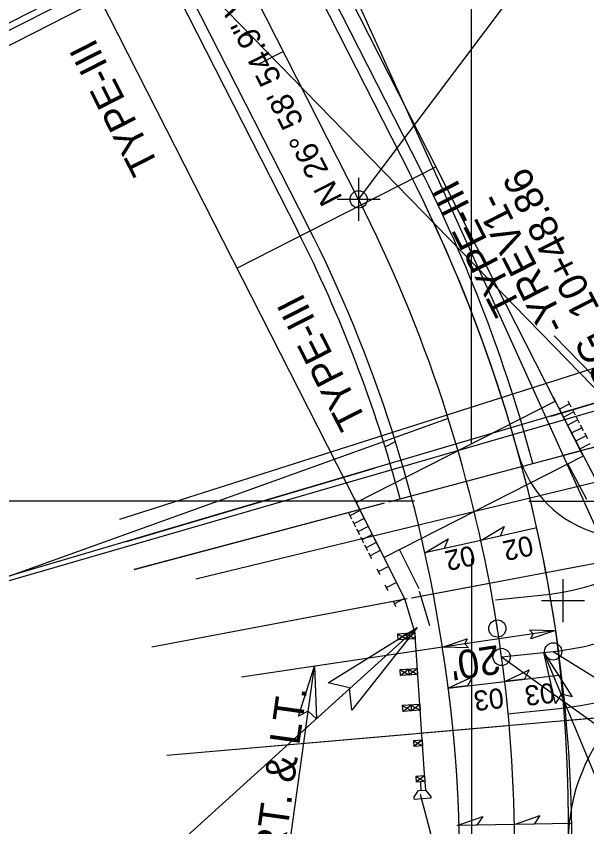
# Model space of a CAD drawing. Extents: x 557583 to 560285, y 513145 to 516544.
# Drawn here: x 559319.8 to 559419.4, y 515400.9 to 515542.3 of the extents above; entities that cross this region are included whole.
import ezdxf

# ---------------------------------------------------------------- set-up
doc = ezdxf.new("R2010")
doc.units = 0
for name, color, linetype in [('COGO Default Chain', 7, 'Continuous'), ('Default', 7, 'Continuous'), ('Exist Environmental Wetland Boundary', 7, 'Continuous'), ('Exist Environmental Wetland Boundary Cogo Point CELL', 7, 'Continuous'), ('Exist Hydro Jurisdictional Stream or Body of Water NEU Mitigable Cogo Comment', 7, 'Continuous'), ('Exist Hydro Jurisdictional Stream or Body of Water NEU Mitigable Cogo Elevation', 7, 'Continuous'), ('Exist Hydro Jurisdictional Stream or Body of Water NEU Mitigable Cogo Point CELL', 7, 'Continuous'), ('Exist Hydro Swamp or Marsh', 7, 'Continuous'), ('Prop Approach Slab', 7, 'Continuous'), ('Prop Dimension', 7, 'Continuous'), ('Prop DSN Text', 7, 'Continuous'), ('Prop EOT', 7, 'Continuous'), ('Prop Guardrail Anchor Unit CELL', 7, 'Continuous'), ('Prop Guardrail Shop Curved', 7, 'Continuous'), ('Prop Paved Shoulder', 7, 'Continuous'), ('Prop Roadway Bridge', 7, 'Continuous'), ('Prop SBG', 7, 'Continuous'), ('Prop Structure Anchor Unit CELL', 7, 'Continuous'), ('Prop Superelevation Label', 7, 'Continuous'), ('Prop Terminator CELL', 7, 'Continuous'), ('Scratch_Level_0', 7, 'Continuous'), ('Scratch_Level_1', 7, 'Continuous'), ('Scratch_Level_2', 7, 'Continuous'), ('Scratch_Level_3', 7, 'Continuous'), ('Scratch_Level_4', 7, 'Continuous'), ('Scratch_Level_6', 7, 'Continuous'), ('Scratch_Level_7', 7, 'Continuous'), ('Scratch_Level_8', 7, 'Continuous')]:
    doc.layers.add(name, color=color, linetype=linetype)

msp = doc.modelspace()

# ---------------------------------------------------------------- linework, layer by layer
at = {"layer": 'COGO Default Chain'}
for p, q in [((559379.56, 515514.07), (559379.56, 515506.57)), ((559383.31, 515510.32), (559375.81, 515510.32)), ((559415.21, 515444.06), (559415.21, 515436.56)), ((559418.96, 515440.31), (559411.46, 515440.31))]:
    msp.add_line(p, q, dxfattribs=at)
msp.add_arc((559156.78, 515396.89), 250, 352.0938, 26.9819, dxfattribs=at)
at = {"layer": 'Default'}
for p, q in [((559399.28, 515467.65), (559399.28, 515704.81)), ((559395.19, 515472.11), (559216.79, 515407.97)), ((559389.28, 515457.65), (558978.6, 515457.65)), ((559409.28, 515457.65), (559788.26, 515457.65)), ((559399.28, 515447.65), (559399.28, 515179.47))]:
    msp.add_line(p, q, dxfattribs=at)
at = {"layer": 'Exist Environmental Wetland Boundary'}
msp.add_line((559403.78, 515435.45), (559402.47, 515443.34), dxfattribs=at)
at = {"layer": 'Exist Environmental Wetland Boundary Cogo Point CELL'}
for p, q in [((559379.56, 515510.32), (559423.68, 515569.02)), ((559425.75, 515397.97), (559411.89, 515431.29)), ((559413.51, 515431.46), (559479.86, 515389.93)), ((559404.51, 515430.5), (559444.86, 515401.63))]:
    msp.add_line(p, q, dxfattribs=at)
for centre in [(559379.56, 515510.32), (559379.56, 515510.32), (559379.56, 515510.32), (559403.78, 515435.45), (559413.51, 515431.46), (559404.51, 515430.5)]:
    msp.add_circle(centre, 1.5, dxfattribs=at)
at = {"layer": 'Exist Hydro Jurisdictional Stream or Body of Water NEU Mitigable Cogo Elevation'}
for p, q in [((559379.56, 515510.32), (559321.14, 515625.08)), ((559404.51, 515430.5), (559413.51, 515431.46)), ((559404.51, 515430.5), (559413.51, 515431.46))]:
    msp.add_line(p, q, dxfattribs=at)
for centre, radius, start, end in [((559156.78, 515396.89), 250, 352.0938, 26.9819), ((559408.21, 515481.18), 50, 276.0894, 314.2836), ((559408.21, 515481.18), 50, 276.0894, 314.2836)]:
    msp.add_arc(centre, radius, start, end, dxfattribs=at)
at = {"layer": 'Exist Hydro Jurisdictional Stream or Body of Water NEU Mitigable Cogo Point CELL'}
for p, q in [((559410.65, 515453), (559400.88, 515450.84)), ((559400.88, 515450.84), (559391.12, 515448.68)), ((559405.05, 515426.2), (559414.98, 515427.37)), ((559395.12, 515425.03), (559405.05, 515426.2)), ((559406.74, 515401.27), (559396.74, 515401.09)), ((559416.74, 515401.44), (559406.74, 515401.27))]:
    msp.add_line(p, q, dxfattribs=at)
for points in [[(559400.88, 515450.84), (559404.96, 515453.28), (559404.27, 515451.59)], [(559391.12, 515448.68), (559395.19, 515451.12), (559394.51, 515449.43)], [(559405.05, 515426.2), (559409.34, 515428.22), (559408.5, 515426.61)], [(559395.12, 515425.03), (559399.41, 515427.05), (559398.57, 515425.43)], [(559396.74, 515401.09), (559401.21, 515402.67), (559400.21, 515401.15)], [(559406.74, 515401.27), (559411.21, 515402.85), (559410.21, 515401.33)]]:
    msp.add_lwpolyline(points, close=True, dxfattribs=at)
at = {"layer": 'Exist Hydro Swamp or Marsh'}
for p, q in [((559366.41, 515536.14), (559361.96, 515533.87)), ((559402.42, 515443.33), (559397.51, 515442.4)), ((559402.42, 515443.33), (559397.51, 515442.4))]:
    msp.add_line(p, q, dxfattribs=at)
at = {"layer": 'Prop Approach Slab'}
for p, q in [((559379.11, 515457.43), (559413.87, 515475.12)), ((559413.87, 515475.12), (559418.75, 515465.54)), ((559418.75, 515465.54), (559383.99, 515447.84)), ((559383.99, 515447.84), (559379.11, 515457.43))]:
    msp.add_line(p, q, dxfattribs=at)
at = {"layer": 'Prop Dimension'}
for p, q in [((559384.16, 515467.16), (559385.97, 515468.08)), ((559389.76, 515435.62), (559326.3, 515378.18)), ((559413.95, 515435.12), (559394.17, 515432.18)), ((559394.17, 515432.18), (559359.08, 515426.96)), ((559367.26, 515395.81), (559371.85, 515428.86))]:
    msp.add_line(p, q, dxfattribs=at)
at = {"layer": 'Prop DSN Text'}
for p, q in [((559379.56, 515514.07), (559379.56, 515506.57)), ((559383.31, 515510.32), (559375.81, 515510.32)), ((559380.26, 515468.4), (559380.26, 515468.4)), ((559415.21, 515444.06), (559415.21, 515436.56)), ((559418.96, 515440.31), (559411.46, 515440.31))]:
    msp.add_line(p, q, dxfattribs=at)
msp.add_arc((559156.78, 515396.89), 250, 352.0938, 26.9819, dxfattribs=at)
at = {"layer": 'Prop EOT'}
for p, q in [((559336.91, 515616.14), (559388.47, 515514.85)), ((559343.16, 515559.77), (559370.65, 515505.78))]:
    msp.add_line(p, q, dxfattribs=at)
for centre, radius, start, end in [((559156.78, 515396.89), 260, 8.4552, 26.9819), ((559156.78, 515396.89), 240, 8.4552, 26.9819), ((559426.71, 515471.29), 20, 195.4097, 314.2835), ((559448.16, 515398.31), 32, 115.7408, 179.4343)]:
    msp.add_arc(centre, radius, start, end, dxfattribs=at)
for points in [[(559415.56, 515383.31), (559415.61, 515384.01), (559415.65, 515384.71), (559415.7, 515385.41), (559415.74, 515386.1), (559415.78, 515386.8), (559415.82, 515387.5), (559415.85, 515388.2), (559415.89, 515388.9), (559415.92, 515389.6), (559415.95, 515390.3), (559415.98, 515391), (559416, 515391.7), (559416.03, 515392.4), (559416.05, 515393.11), (559416.07, 515393.81), (559416.09, 515394.51), (559416.11, 515395.21), (559416.12, 515395.91), (559416.14, 515396.61), (559416.15, 515397.31), (559416.16, 515398.01), (559416.17, 515398.71), (559416.17, 515399.41), (559416.17, 515400.11), (559416.18, 515400.82), (559416.18, 515401.52), (559416.17, 515402.22), (559416.17, 515402.92), (559416.17, 515403.62), (559416.16, 515404.32), (559416.15, 515405.02), (559416.14, 515405.73), (559416.12, 515406.43), (559416.11, 515407.13), (559416.09, 515407.83), (559416.07, 515408.53), (559416.05, 515409.23), (559416.03, 515409.93), (559416, 515410.63), (559415.98, 515411.34), (559415.95, 515412.04), (559415.92, 515412.74), (559415.89, 515413.44), (559415.85, 515414.14), (559415.82, 515414.84), (559415.78, 515415.54), (559415.74, 515416.24), (559415.7, 515416.94), (559415.65, 515417.64), (559415.61, 515418.34), (559415.56, 515419.04), (559415.51, 515419.75), (559415.46, 515420.45), (559415.41, 515421.15), (559415.35, 515421.85), (559415.3, 515422.55), (559415.24, 515423.25), (559415.18, 515423.95), (559415.11, 515424.64), (559415.05, 515425.34), (559414.98, 515426.04), (559414.92, 515426.74), (559414.85, 515427.44), (559414.77, 515428.14), (559414.7, 515428.84), (559414.62, 515429.54), (559414.55, 515430.24), (559414.47, 515430.93), (559414.39, 515431.63), (559414.3, 515432.33), (559414.22, 515433.03), (559414.13, 515433.72), (559413.95, 515435.12)], [(559397, 515384.28), (559397.02, 515384.93), (559397.05, 515385.58), (559397.07, 515386.23), (559397.09, 515386.88), (559397.11, 515387.53), (559397.12, 515388.18), (559397.14, 515388.83), (559397.15, 515389.48), (559397.16, 515390.13), (559397.17, 515390.78), (559397.18, 515391.43), (559397.19, 515392.08), (559397.19, 515392.73), (559397.2, 515393.38), (559397.2, 515394.03), (559397.2, 515394.68), (559397.19, 515395.33), (559397.19, 515395.98), (559397.18, 515396.63), (559397.18, 515397.28), (559397.17, 515397.93), (559397.16, 515398.58), (559397.14, 515399.23), (559397.13, 515399.88), (559397.11, 515400.53), (559397.09, 515401.18), (559397.07, 515401.83), (559397.05, 515402.48), (559397.03, 515403.12), (559397, 515403.77), (559396.98, 515404.42), (559396.95, 515405.07), (559396.92, 515405.72), (559396.89, 515406.37), (559396.85, 515407.02), (559396.82, 515407.67), (559396.78, 515408.31), (559396.74, 515408.96), (559396.7, 515409.61), (559396.66, 515410.26), (559396.61, 515410.91), (559396.57, 515411.55), (559396.52, 515412.2), (559396.47, 515412.85), (559396.42, 515413.5), (559396.36, 515414.14), (559396.31, 515414.79), (559396.25, 515415.44), (559396.19, 515416.08), (559396.13, 515416.73), (559396.07, 515417.38), (559396.01, 515418.02), (559395.94, 515418.67), (559395.88, 515419.31), (559395.81, 515419.96), (559395.74, 515420.6), (559395.66, 515421.25), (559395.59, 515421.89), (559395.51, 515422.54), (559395.44, 515423.18), (559395.36, 515423.83), (559395.28, 515424.47), (559395.19, 515425.11), (559395.11, 515425.76), (559395.02, 515426.4), (559394.93, 515427.04), (559394.84, 515427.69), (559394.75, 515428.33), (559394.66, 515428.97), (559394.56, 515429.61), (559394.47, 515430.25), (559394.37, 515430.9), (559394.17, 515432.18)]]:
    msp.add_spline(points, degree=3, dxfattribs=at)
at = {"layer": 'Prop Guardrail Anchor Unit CELL'}
for p, q in [((559389.36, 515434.68), (559386.33, 515434.47)), ((559387.92, 515433.58), (559386.33, 515434.47)), ((559386.33, 515434.47), (559386.4, 515433.47)), ((559386.4, 515433.47), (559387.85, 515434.57)), ((559389.43, 515433.68), (559386.4, 515433.47)), ((559387.85, 515434.57), (559387.92, 515433.58)), ((559387.85, 515434.57), (559389.43, 515433.68)), ((559389.36, 515434.68), (559387.92, 515433.58)), ((559389.36, 515434.68), (559389.43, 515433.68)), ((559391.09, 515409.23), (559389.4, 515434.18)), ((559389.79, 515428.44), (559386.76, 515428.24)), ((559388.34, 515427.34), (559386.76, 515428.24)), ((559386.76, 515428.24), (559386.82, 515427.24)), ((559386.82, 515427.24), (559388.27, 515428.34)), ((559388.27, 515428.34), (559388.34, 515427.34)), ((559388.27, 515428.34), (559389.85, 515427.44)), ((559389.79, 515428.44), (559388.34, 515427.34)), ((559389.79, 515428.44), (559389.85, 515427.44)), ((559389.85, 515427.44), (559386.82, 515427.24)), ((559390.21, 515422.2), (559387.18, 515422)), ((559390.21, 515422.2), (559388.76, 515421.1)), ((559390.21, 515422.2), (559390.28, 515421.21)), ((559388.76, 515421.1), (559387.18, 515422)), ((559387.18, 515422), (559387.25, 515421)), ((559387.25, 515421), (559388.69, 515422.1)), ((559390.28, 515421.21), (559387.25, 515421)), ((559388.69, 515422.1), (559388.76, 515421.1)), ((559388.69, 515422.1), (559390.28, 515421.21)), ((559390.63, 515415.97), (559389.12, 515415.87)), ((559389.12, 515415.87), (559389.18, 515414.87)), ((559389.12, 515415.87), (559390.7, 515414.97)), ((559390.63, 515415.97), (559389.18, 515414.87)), ((559390.63, 515415.97), (559390.7, 515414.97)), ((559390.7, 515414.97), (559389.18, 515414.87)), ((559391.05, 515409.73), (559389.54, 515409.63)), ((559389.54, 515409.63), (559389.61, 515408.63)), ((559389.54, 515409.63), (559391.12, 515408.74)), ((559391.05, 515409.73), (559389.61, 515408.63)), ((559391.05, 515409.73), (559391.12, 515408.74)), ((559391.12, 515408.74), (559389.61, 515408.63)), ((559390.49, 515407.22), (559390.39, 515408.69)), ((559391.11, 515408.73), (559391.21, 515407.27)), ((559389.21, 515405.96), (559389.99, 515407.19)), ((559389.99, 515407.19), (559391.21, 515407.27)), ((559391.21, 515407.27), (559392.14, 515406.15)), ((559389.21, 515405.96), (559389.23, 515405.65)), ((559392.16, 515405.84), (559389.23, 515405.65)), ((559392.14, 515406.15), (559392.16, 515405.84))]:
    msp.add_line(p, q, dxfattribs=at)
at = {"layer": 'Prop Guardrail Shop Curved'}
msp.add_line((559387.58, 515440.69), (559389.36, 515434.68), dxfattribs=at)
at = {"layer": 'Prop Paved Shoulder'}
msp.add_line((559390.29, 515406.56), (559396.87, 515381.68), dxfattribs=at)
at = {"layer": 'Prop Roadway Bridge'}
for p, q in [((559413.87, 515475.12), (559367.54, 515566.11)), ((559332.79, 515548.41), (559379.11, 515457.43)), ((559358.28, 515498.34), (559393.04, 515516.03)), ((559379.11, 515457.43), (559413.87, 515475.12))]:
    msp.add_line(p, q, dxfattribs=at)
at = {"layer": 'Prop SBG'}
for p, q in [((559419.38, 515457.96), (559416.09, 515464.18)), ((559386.67, 515449.21), (559390.05, 515442.46)), ((559390.14, 515442), (559391.92, 515435.98))]:
    msp.add_line(p, q, dxfattribs=at)
at = {"layer": 'Prop Structure Anchor Unit CELL'}
for p, q in [((559413.87, 515475.12), (559422.47, 515458.46)), ((559414.58, 515473.73), (559416.36, 515474.65)), ((559416.1, 515475.16), (559416.62, 515474.14)), ((559415.3, 515472.34), (559417.08, 515473.26)), ((559416.81, 515473.77), (559417.34, 515472.75)), ((559416.02, 515470.96), (559417.79, 515471.87)), ((559417.53, 515472.38), (559418.06, 515471.36)), ((559416.73, 515469.57), (559418.51, 515470.48)), ((559418.25, 515470.99), (559418.77, 515469.98)), ((559417.45, 515468.18), (559419.23, 515469.1)), ((559418.97, 515469.61), (559419.49, 515468.59)), ((559418.17, 515466.79), (559419.95, 515467.71)), ((559379.11, 515457.43), (559387.58, 515440.69)), ((559377.77, 515455.64), (559378.29, 515454.62)), ((559379.82, 515456.03), (559378.03, 515455.13)), ((559378.48, 515454.25), (559379, 515453.22)), ((559380.52, 515454.64), (559378.74, 515453.73)), ((559379.18, 515452.85), (559379.7, 515451.83)), ((559381.23, 515453.24), (559379.44, 515452.34)), ((559379.89, 515451.46), (559380.41, 515450.43)), ((559381.93, 515451.85), (559380.15, 515450.95)), ((559382.64, 515450.45), (559380.85, 515449.55)), ((559380.59, 515450.06), (559381.11, 515449.04)), ((559383.34, 515449.06), (559381.56, 515448.16)), ((559381.3, 515448.67), (559381.82, 515447.65)), ((559384.75, 515446.27), (559382.97, 515445.37)), ((559382.71, 515445.88), (559383.23, 515444.86)), ((559386.16, 515443.48), (559384.38, 515442.58)), ((559384.12, 515443.09), (559384.64, 515442.07)), ((559387.58, 515440.69), (559385.79, 515439.79)), ((559385.53, 515440.3), (559386.05, 515439.28))]:
    msp.add_line(p, q, dxfattribs=at)
at = {"layer": 'Prop Terminator CELL'}
for points in [[(559374.25, 515425.99), (559389.76, 515435.62), (559378.35, 515421.21), (559377.95, 515425.13)], [(559409.38, 515435.22), (559413.95, 515435.12), (559409.59, 515433.66), (559410.04, 515434.54)], [(559398.73, 515432.07), (559394.17, 515432.18), (559398.53, 515433.63), (559398.07, 515432.76)], [(559413.92, 515422.39), (559411.89, 515431.29), (559416.85, 515423.55), (559414.93, 515424)], [(559369.08, 515420.16), (559371.85, 515428.86), (559372.19, 515419.68), (559370.77, 515421.04)]]:
    msp.add_lwpolyline(points, close=True, dxfattribs=at)
at = {"layer": 'Scratch_Level_0'}
for p, q in [((559361.38, 515572.48), (559390.26, 515515.76)), ((559341.38, 515558.86), (559368.87, 515504.87))]:
    msp.add_line(p, q, dxfattribs=at)
for radius in [262, 238]:
    msp.add_arc((559156.78, 515396.89), radius, 14.8991, 26.9819, dxfattribs=at)
at = {"layer": 'Scratch_Level_1'}
for p, q in [((559302.66, 515529.12), (559409.6, 515583.57)), ((559301.6, 515531.2), (559338.67, 515550.07)), ((559452.18, 515490.88), (559337.83, 515454.5)), ((559413.17, 515472.52), (559454.11, 515484.6)), ((559456.35, 515476.6), (559415.02, 515465.6)), ((559339.01, 515450.65), (559382.3, 515463.41)), ((559384.01, 515457.35), (559340.39, 515445.74)), ((559419.03, 515446.47), (559388.77, 515440.75)), ((559388.04, 515440.61), (559343.47, 515432.18)), ((559346.06, 515413.37), (559404.99, 515418.5))]:
    msp.add_line(p, q, dxfattribs=at)
at = {"layer": 'Scratch_Level_2'}
msp.add_arc((559156.78, 515396.89), 260, 352.0938, 26.9819, dxfattribs=at)
at = {"layer": 'Scratch_Level_3'}
for p, q in [((559587.3, 515306.64), (559308.02, 515593)), ((559413.66, 515486.5), (559433.14, 515466.53)), ((559403.44, 515440.45), (559412.45, 515441.41)), ((559405.57, 515420.56), (559414.57, 515421.52))]:
    msp.add_line(p, q, dxfattribs=at)
for centre, radius, start, end in [((559156.78, 515396.89), 260, 352.0938, 26.9819), ((559408.21, 515481.18), 40, 276.0894, 314.2836), ((559408.21, 515481.18), 60, 276.0894, 314.2836)]:
    msp.add_arc(centre, radius, start, end, dxfattribs=at)
at = {"layer": 'Scratch_Level_4'}
for p, q in [((559972.04, 515637.38), (559406.15, 515470.45)), ((559413.45, 515475.93), (559422.06, 515459.27)), ((559418.57, 515466.55), (559456.35, 515476.6)), ((559406.15, 515470.45), (558821.08, 515297.86)), ((559384.82, 515457.57), (559418.27, 515466.47)), ((559378.7, 515458.24), (559387.16, 515441.51)), ((559340.39, 515445.74), (559379.68, 515456.2)), ((559379.73, 515456.21), (559383.46, 515457.2)), ((559461.38, 515454.48), (559388.86, 515440.77)), ((559387.46, 515440.5), (559343.47, 515432.18)), ((559390.19, 515417.21), (559465.61, 515423.78)), ((559346.06, 515413.37), (559387.58, 515416.98))]:
    msp.add_line(p, q, dxfattribs=at)
at = {"layer": 'Scratch_Level_6'}
for p, q in [((559265.42, 515514.11), (559443.65, 515604.85)), ((559492.94, 515494.32), (559300.85, 515438.64)), ((559448.31, 515467.64), (559351.13, 515444.06))]:
    msp.add_line(p, q, dxfattribs=at)
at = {"layer": 'Scratch_Level_7'}
for p, q in [((559415.54, 515419.42), (559421.79, 515419.96)), ((559346.06, 515413.37), (559388.39, 515417.05)), ((559390.19, 515417.21), (559396.04, 515417.72))]:
    msp.add_line(p, q, dxfattribs=at)
at = {"layer": 'Scratch_Level_8'}
msp.add_line((559428.04, 515437.39), (559305.09, 515708.93), dxfattribs=at)

# ---------------------------------------------------------------- texts
at = {"layer": 'Exist Hydro Jurisdictional Stream or Body of Water NEU Mitigable Cogo Comment'}
msp.add_text('N 26%%d 58\' 54.9" W', height=4, rotation=116.9819, dxfattribs=at).set_placement((559376.82, 515510.54))
at = {"layer": 'Prop Dimension'}
msp.add_text("100' TAPER RT. & LT.", height=5.25, rotation=82.0938, dxfattribs=at).set_placement((559360.9, 515355.28))
at = {"layer": 'Prop DSN Text'}
for s, rotation, p in [('10+48.86', 117.0233, (559421.72, 515491.26)), ('-YREV1-', 117.0233, (559416.08, 515488.38)), ('BEG SBG', 117.0233, (559435.09, 515461.04)), ("20'", 188.4552, (559403.87, 515432.59))]:
    msp.add_text(s, height=5, rotation=rotation, dxfattribs=at).set_placement(p)
at = {"layer": 'Prop Structure Anchor Unit CELL'}
for p in [(559344.8, 515516.15), (559408.02, 515491.62), (559381.02, 515471.72)]:
    msp.add_text('TYPE-III', height=5, rotation=116.9819, dxfattribs=at).set_placement(p)
at = {"layer": 'Prop Superelevation Label'}
for s, rotation, p in [('02', 192.4629, (559409.56, 515451.73)), ('02', 192.4629, (559399.45, 515450)), ('03', 186.7333, (559404.66, 515425.12)), ('03', 186.7333, (559413.56, 515426.02))]:
    msp.add_text(s, height=3.5, rotation=rotation, dxfattribs=at).set_placement(p)

doc.saveas('drawing.dxf')
